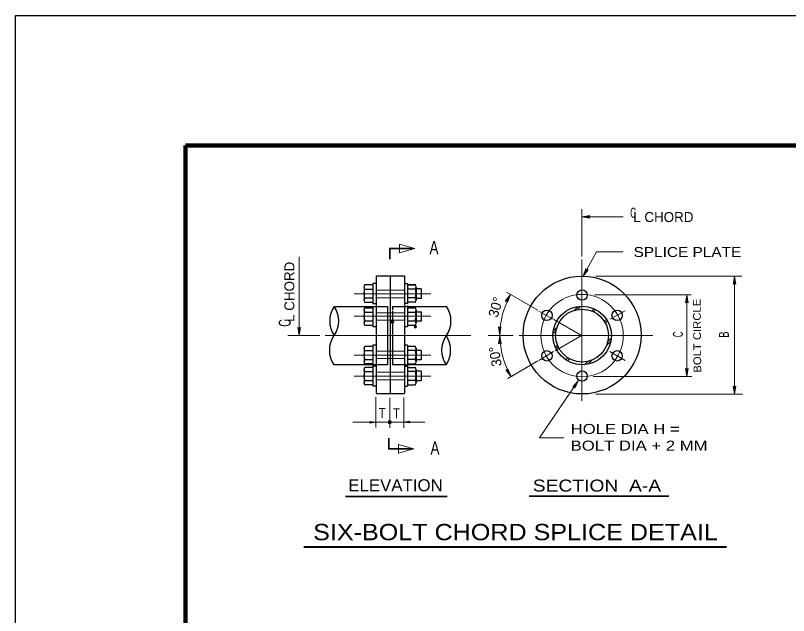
# Model space of a CAD drawing. Extents: x 312601.858 to 312602.699, y 144420.109 to 144420.704.
# Drawn here: x 312601.8578 to 312602.0898, y 144420.5234 to 144420.7035 of the extents above; entities that cross this region are included whole.
import ezdxf
from ezdxf.enums import TextEntityAlignment as Align

# ---------------------------------------------------------------- set-up
doc = ezdxf.new("R2010")
doc.units = 0
doc.header["$LTSCALE"] = 0.0012
doc.header["$PDMODE"] = 32
doc.header["$PDSIZE"] = 0.0006
for name, pattern in [('DOT_DASHED', [7.7, 5, -1.2, 0.3, -1.2]), ('LONG_DASHED', [7.5, 6, -1.5]), ('MEDIUM_DASHED', [4.5, 3, -1.5]), ('SHORT_DASHED', [2.7, 1.5, -1.2])]:
    doc.linetypes.add(name, pattern=pattern)
for name, color, linetype, lineweight in [('1', 7, 'Continuous', 25), ('2', 7, 'Continuous', 13), ('39', 7, 'Continuous', 13), ('9', 7, 'Continuous', 13)]:
    doc.layers.add(name, color=color, linetype=linetype, lineweight=lineweight)

msp = doc.modelspace()

# ---------------------------------------------------------------- hatches: boundary and pattern name
at = {"layer": '1'}
msp.add_hatch(color=256, dxfattribs=at).paths.add_polyline_path([(312601.97063, 144420.58144, 1), (312601.96961, 144420.58144, 1)])
at = {"layer": '39'}
for points in [[(312602.03, 144420.6431), (312602.0302, 144420.6427), (312602.0278, 144420.6431), (312602.0302, 144420.6435)], [(312602.0292, 144420.6272), (312602.0297, 144420.6272), (312602.0282, 144420.6253), (312602.029, 144420.6276)], [(312602.0736, 144420.6231), (312602.0732, 144420.6229), (312602.0736, 144420.6253), (312602.074, 144420.6229)], [(312602.0736, 144420.6231), (312602.0732, 144420.6229), (312602.0736, 144420.6253), (312602.074, 144420.6229)], [(312602.0053, 144420.6178), (312602.0048, 144420.6178), (312602.0064, 144420.6198), (312602.0055, 144420.6174)], [(312602.0593, 144420.6175), (312602.0589, 144420.6173), (312602.0593, 144420.6197), (312602.0597, 144420.6173)], [(312601.9429, 144420.6096), (312601.9433, 144420.6098), (312601.9429, 144420.6074), (312601.9425, 144420.6098)], [(312601.9429, 144420.6096), (312601.9433, 144420.6098), (312601.9429, 144420.6074), (312601.9425, 144420.6098)], [(312602.0032, 144420.6097), (312602.0035, 144420.61), (312602.0032, 144420.6074), (312602.0028, 144420.61)], [(312602.0032, 144420.6051), (312602.0028, 144420.6049), (312602.0032, 144420.6074), (312602.0036, 144420.6049)], [(312602.0054, 144420.5971), (312602.0056, 144420.5974), (312602.0066, 144420.595), (312602.005, 144420.5971)], [(312602.0593, 144420.5973), (312602.0597, 144420.5975), (312602.0593, 144420.5951), (312602.0589, 144420.5975)], [(312602.0255, 144420.592), (312602.0251, 144420.592), (312602.0267, 144420.5938), (312602.0257, 144420.5916)], [(312602.0255, 144420.592), (312602.0251, 144420.592), (312602.0267, 144420.5938), (312602.0257, 144420.5916)], [(312602.0736, 144420.592), (312602.074, 144420.5922), (312602.0736, 144420.5898), (312602.0732, 144420.5922)], [(312602.0736, 144420.592), (312602.074, 144420.5922), (312602.0736, 144420.5898), (312602.0732, 144420.5922)]]:
    msp.add_hatch(color=256, dxfattribs=at).paths.add_polyline_path(points)

# ---------------------------------------------------------------- linework, layer by layer
at = {"layer": '1', "lineweight": 13}
for p, q in [((312602.0278, 144420.6312), (312602.0278, 144420.6454)), ((312602.0278, 144420.6431), (312602.0402, 144420.6431)), ((312601.9429, 144420.6074), (312601.9429, 144420.6311)), ((312602.0322, 144420.6326), (312602.0282, 144420.6253)), ((312602.0322, 144420.6326), (312602.0402, 144420.6326)), ((312602.032, 144420.6253), (312602.0758, 144420.6253)), ((312602.0736, 144420.5898), (312602.0736, 144420.6253)), ((312601.9795, 144420.6213), (312601.9795, 144420.6215)), ((312602.0146, 144420.6151), (312602.0052, 144420.6205)), ((312602.0316, 144420.6197), (312602.0606, 144420.6197)), ((312602.0593, 144420.5951), (312602.0593, 144420.6197)), ((312601.9744, 144420.6162), (312601.9745, 144420.6162)), ((312602.0277, 144420.6074), (312602.0194, 144420.6122)), ((312601.9997, 144420.6074), (312602.0072, 144420.6074)), ((312602.0277, 144420.6074), (312602.0198, 144420.6028)), ((312601.9795, 144420.6028), (312601.9795, 144420.6029)), ((312601.9771, 144420.5989), (312601.9754, 144420.5989)), ((312602.0146, 144420.5998), (312602.0056, 144420.5945)), ((312601.9795, 144420.5965), (312601.9795, 144420.5967)), ((312602.0312, 144420.5951), (312602.0608, 144420.5951)), ((312602.0151, 144420.5767), (312602.0267, 144420.5938)), ((312602.032, 144420.5898), (312602.076, 144420.5898)), ((312601.9659, 144420.5889), (312601.9659, 144420.5798)), ((312601.9701, 144420.5887), (312601.9701, 144420.5797)), ((312601.9743, 144420.5888), (312601.9743, 144420.5797)), ((312601.959, 144420.5814), (312601.9806, 144420.5814))]:
    msp.add_line(p, q, dxfattribs=at)
at = {"layer": '1', "linetype": 'DOT_DASHED', "lineweight": 13}
for p, q in [((312602.0278, 144420.5878), (312602.0278, 144420.6303)), ((312602.0278, 144420.6171), (312602.0278, 144420.6224)), ((312601.9825, 144420.62), (312601.9594, 144420.62)), ((312602.0192, 144420.6123), (312602.0149, 144420.6148)), ((312602.0362, 144420.6123), (312602.0408, 144420.6149)), ((312601.9594, 144420.6132), (312601.9825, 144420.6132)), ((312602.009, 144420.6074), (312602.0491, 144420.6074)), ((312601.9594, 144420.6015), (312601.9825, 144420.6015)), ((312602.0193, 144420.6026), (312602.0149, 144420.5999)), ((312602.0362, 144420.6026), (312602.0408, 144420.5999)), ((312602.0278, 144420.5977), (312602.0278, 144420.5925)), ((312601.9825, 144420.5952), (312601.9594, 144420.5952))]:
    msp.add_line(p, q, dxfattribs=at)
at = {"layer": '1'}
for p, q in [((312601.966, 144420.6254), (312601.9745, 144420.6254)), ((312601.9745, 144420.6254), (312601.9745, 144420.6162)), ((312601.9624, 144420.622), (312601.9624, 144420.6181)), ((312601.965, 144420.6227), (312601.9626, 144420.6227)), ((312601.965, 144420.6231), (312601.965, 144420.6215)), ((312601.966, 144420.6231), (312601.965, 144420.6231)), ((312601.9745, 144420.6231), (312601.9754, 144420.6231)), ((312601.9754, 144420.6231), (312601.9754, 144420.6215)), ((312601.9754, 144420.6227), (312601.9778, 144420.6227)), ((312601.9779, 144420.6227), (312601.9754, 144420.6227)), ((312601.978, 144420.622), (312601.978, 144420.6181)), ((312601.9626, 144420.6214), (312601.965, 144420.6214)), ((312601.965, 144420.6215), (312601.965, 144420.6171)), ((312601.966, 144420.621), (312601.966, 144420.6162)), ((312601.9754, 144420.6215), (312601.9754, 144420.6171)), ((312601.9779, 144420.6214), (312601.9754, 144420.6214)), ((312601.9795, 144420.6215), (312601.978, 144420.6215)), ((312601.9795, 144420.6215), (312601.9795, 144420.6186)), ((312601.9625, 144420.6175), (312601.965, 144420.6175)), ((312601.9626, 144420.6188), (312601.965, 144420.6188)), ((312601.965, 144420.6171), (312601.966, 144420.6171)), ((312601.9754, 144420.6171), (312601.9745, 144420.6171)), ((312601.9778, 144420.6188), (312601.9754, 144420.6188)), ((312601.9779, 144420.6175), (312601.9754, 144420.6175)), ((312601.9795, 144420.6186), (312601.978, 144420.6186)), ((312601.9535, 144420.6162), (312601.966, 144420.6162)), ((312601.9624, 144420.6151), (312601.9624, 144420.6112)), ((312601.9626, 144420.6162), (312601.965, 144420.6162)), ((312601.9626, 144420.6158), (312601.965, 144420.6158)), ((312601.965, 144420.6162), (312601.965, 144420.6101)), ((312601.9745, 144420.6162), (312601.9873, 144420.6162)), ((312601.9754, 144420.6165), (312601.9754, 144420.6164)), ((312601.9754, 144420.6162), (312601.9754, 144420.6101)), ((312601.9754, 144420.6158), (312601.9778, 144420.6158)), ((312601.978, 144420.6151), (312601.978, 144420.6112)), ((312601.9626, 144420.6145), (312601.965, 144420.6145)), ((312601.9754, 144420.6145), (312601.9778, 144420.6145)), ((312601.9626, 144420.6118), (312601.965, 144420.6118)), ((312601.9626, 144420.6105), (312601.965, 144420.6105)), ((312601.965, 144420.6104), (312601.965, 144420.6101)), ((312601.965, 144420.6101), (312601.966, 144420.6101)), ((312601.966, 144420.6118), (312601.966, 144420.6115)), ((312601.966, 144420.6115), (312601.966, 144420.5901)), ((312601.9702, 144420.6118), (312601.9702, 144420.6115)), ((312601.9702, 144420.6115), (312601.9702, 144420.59)), ((312601.9745, 144420.6117), (312601.9745, 144420.6114)), ((312601.9745, 144420.6114), (312601.9745, 144420.5901)), ((312601.9745, 144420.6101), (312601.9754, 144420.6101)), ((312601.9754, 144420.6118), (312601.9778, 144420.6118)), ((312601.9754, 144420.6106), (312601.9754, 144420.6103)), ((312601.9754, 144420.6105), (312601.9778, 144420.6105)), ((312601.9624, 144420.6035), (312601.9624, 144420.5995)), ((312601.965, 144420.6041), (312601.9626, 144420.6041)), ((312601.966, 144420.6045), (312601.965, 144420.6045)), ((312601.9754, 144420.6045), (312601.9745, 144420.6045)), ((312601.9778, 144420.6041), (312601.9754, 144420.6041)), ((312601.978, 144420.6035), (312601.978, 144420.5995)), ((312601.9626, 144420.6029), (312601.965, 144420.6029)), ((312601.9779, 144420.6029), (312601.9754, 144420.6029)), ((312601.9795, 144420.6029), (312601.978, 144420.6029)), ((312601.978, 144420.6001), (312601.978, 144420.6029)), ((312601.9795, 144420.6029), (312601.9795, 144420.6001)), ((312601.965, 144420.5986), (312601.9534, 144420.5986)), ((312601.9626, 144420.6002), (312601.965, 144420.6002)), ((312601.965, 144420.5989), (312601.9626, 144420.5989)), ((312601.966, 144420.5985), (312601.965, 144420.5985)), ((312601.9754, 144420.5985), (312601.9745, 144420.5985)), ((312601.9778, 144420.6002), (312601.9754, 144420.6002)), ((312601.9754, 144420.5989), (312601.9778, 144420.5989)), ((312601.987, 144420.5986), (312601.9754, 144420.5986)), ((312601.9795, 144420.6001), (312601.978, 144420.6001)), ((312601.9624, 144420.5972), (312601.9624, 144420.5933)), ((312601.965, 144420.5978), (312601.9626, 144420.5978)), ((312601.9626, 144420.5966), (312601.965, 144420.5966)), ((312601.966, 144420.5982), (312601.965, 144420.5982)), ((312601.9745, 144420.5982), (312601.9754, 144420.5982)), ((312601.9754, 144420.5978), (312601.9778, 144420.5978)), ((312601.9779, 144420.5966), (312601.9754, 144420.5966)), ((312601.978, 144420.5972), (312601.978, 144420.5933)), ((312601.9795, 144420.5967), (312601.978, 144420.5967)), ((312601.9795, 144420.5967), (312601.9795, 144420.5938)), ((312601.9626, 144420.5939), (312601.965, 144420.5939)), ((312601.9778, 144420.5939), (312601.9754, 144420.5939)), ((312601.965, 144420.5926), (312601.9626, 144420.5926)), ((312601.966, 144420.5922), (312601.965, 144420.5922)), ((312601.9745, 144420.5922), (312601.9754, 144420.5922)), ((312601.9754, 144420.5926), (312601.9778, 144420.5926)), ((312601.9795, 144420.5938), (312601.978, 144420.5938)), ((312601.966, 144420.59), (312601.9745, 144420.59))]:
    msp.add_line(p, q, dxfattribs=at)
at = {"layer": '1', "linetype": 'MEDIUM_DASHED', "lineweight": 13}
for p, q in [((312601.9745, 144420.6211), (312601.966, 144420.6211)), ((312601.9745, 144420.6188), (312601.966, 144420.6188)), ((312601.9662, 144420.6143), (312601.9743, 144420.6143)), ((312601.9663, 144420.612), (312601.9743, 144420.612)), ((312601.9746, 144420.6027), (312601.9661, 144420.6027)), ((312601.9747, 144420.6005), (312601.9662, 144420.6005)), ((312601.9744, 144420.5964), (312601.9659, 144420.5964)), ((312601.9745, 144420.5941), (312601.966, 144420.5941))]:
    msp.add_line(p, q, dxfattribs=at)
at = {"layer": '1', "linetype": 'LONG_DASHED'}
for p, q in [((312601.9653, 144420.6162), (312601.9694, 144420.6162)), ((312601.9709, 144420.6162), (312601.9752, 144420.6162)), ((312601.9709, 144420.6162), (312601.9709, 144420.6151)), ((312601.9709, 144420.6148), (312601.9709, 144420.6114)), ((312601.9694, 144420.6118), (312601.9694, 144420.6115)), ((312601.9694, 144420.6115), (312601.9694, 144420.5986)), ((312601.9709, 144420.6117), (312601.9709, 144420.6114)), ((312601.9709, 144420.6114), (312601.9709, 144420.5986)), ((312601.9694, 144420.5986), (312601.9654, 144420.5986)), ((312601.975, 144420.5986), (312601.9709, 144420.5986))]:
    msp.add_line(p, q, dxfattribs=at)
at = {"layer": '1', "linetype": 'SHORT_DASHED', "lineweight": 13}
msp.add_line((312601.9754, 144420.5989), (312601.9771, 144420.5989), dxfattribs=at)
at = {"layer": '1', "lineweight": 35}
for points in [[(312601.9771, 144420.6336), (312601.9701, 144420.6336), (312601.9701, 144420.6304)], [(312601.9768, 144420.5734), (312601.9698, 144420.5734), (312601.9698, 144420.5766)]]:
    msp.add_lwpolyline(points, dxfattribs=at)
at = {"layer": '1'}
for points in [[(312601.966, 144420.6254), (312601.966, 144420.6237), (312601.966, 144420.621)], [(312601.9702, 144420.6254), (312601.9702, 144420.6151), (312601.9702, 144420.6115)], [(312601.966, 144420.6162), (312601.966, 144420.6151), (312601.966, 144420.6115)], [(312601.9745, 144420.6162), (312601.9745, 144420.6151), (312601.9745, 144420.6114)], [(312601.965, 144420.6045), (312601.965, 144420.5985), (312601.965, 144420.5922)], [(312601.9754, 144420.6045), (312601.9754, 144420.5985), (312601.9754, 144420.5922)]]:
    msp.add_lwpolyline(points, dxfattribs=at)
at = {"layer": '1', "linetype": 'LONG_DASHED'}
msp.add_lwpolyline([(312601.9694, 144420.6162), (312601.9694, 144420.6151), (312601.9694, 144420.6115)], dxfattribs=at)
at = {"layer": '1'}
for centre, radius in [((312602.02783, 144420.60759), 0.017693), ((312602.02783, 144420.619575), 0.00156), ((312602.017303, 144420.613498), 0.00156), ((312602.02783, 144420.60742), 0.008788), ((312602.02783, 144420.60742), 0.007942), ((312602.038357, 144420.613498), 0.00156), ((312602.017303, 144420.601343), 0.00156), ((312602.038357, 144420.601343), 0.00156), ((312602.02783, 144420.595265), 0.00156)]:
    msp.add_circle(centre, radius, dxfattribs=at)
at = {"layer": '1', "linetype": 'DOT_DASHED', "lineweight": 13}
msp.add_circle((312602.02783, 144420.60742), 0.012354, dxfattribs=at)
at = {"layer": '1', "lineweight": 13}
msp.add_circle((312601.97012, 144420.58144), 0.00051, dxfattribs=at)
at = {"layer": '1'}
for centre, radius, start, end in [((312601.96349, 144420.621985), 0.001105, 142.02013, 212.47565), ((312601.97692, 144420.621985), 0.001105, 327.52435, 37.97987), ((312601.97386, 144420.6202), 0.004169, 339.71744, 16.58734), ((312601.96349, 144420.618075), 0.001105, 142.02013, 211.35654), ((312601.97692, 144420.618075), 0.001105, 328.64346, 37.97987), ((312601.96349, 144420.615155), 0.001105, 144.28806, 217.97987), ((312601.97692, 144420.615165), 0.001105, 323.00036, 35.07587), ((312601.96655, 144420.61328), 0.004169, 162.98192, 200.79629), ((312601.97386, 144420.61328), 0.004169, 339.98134, 17.62585), ((312601.96349, 144420.611155), 0.001105, 142.02013, 217.97987), ((312601.97692, 144420.611155), 0.001105, 322.02013, 35.71194), ((312601.96349, 144420.603455), 0.001105, 142.02013, 212.47565), ((312601.97692, 144420.603455), 0.001105, 327.52435, 37.97987), ((312601.96655, 144420.60167), 0.004169, 163.41266, 200.28256), ((312601.97386, 144420.60167), 0.004169, 339.71744, 16.58734), ((312601.96349, 144420.599545), 0.001105, 142.02013, 217.97987), ((312601.97692, 144420.599545), 0.001105, 322.02013, 37.97987), ((312601.96655, 144420.59538), 0.004169, 163.41266, 200.28256), ((312601.96349, 144420.597165), 0.001105, 144.92413, 212.47565), ((312601.97386, 144420.59538), 0.004169, 339.71744, 16.58734), ((312601.97692, 144420.597165), 0.001105, 327.52435, 35.07587), ((312601.96349, 144420.593255), 0.001105, 142.02013, 217.97987), ((312601.97692, 144420.593255), 0.001105, 322.02013, 37.97987)]:
    msp.add_arc(centre, radius, start, end, dxfattribs=at)
at = {"layer": '1', "lineweight": 13}
for centre, radius, start, end in [((312601.96655, 144420.6202), 0.004169, 163.41266, 200.28256), ((312602.02783, 144420.60759), 0.024638, 150.28424, 180.39609), ((312602.02783, 144420.60759), 0.024638, 180.39533, 210.59712)]:
    msp.add_arc(centre, radius, start, end, dxfattribs=at)
at = {"layer": '1'}
for p in [(312601.9709, 144420.6115), (312601.9709, 144420.6114)]:
    msp.add_point(p, dxfattribs=at)
at = {"layer": '2'}
for p, q in [((312602.0255, 144420.615), (312602.0266, 144420.6161)), ((312602.0264, 144420.6152), (312602.0274, 144420.6162)), ((312602.0308, 144420.6148), (312602.0314, 144420.6154)), ((312602.0313, 144420.6146), (312602.0319, 144420.6152)), ((312602.0346, 144420.6117), (312602.0352, 144420.6123)), ((312602.0349, 144420.6112), (312602.0355, 144420.6118)), ((312602.0191, 144420.6086), (312602.0203, 144420.6098)), ((312602.0191, 144420.6079), (312602.0201, 144420.6089)), ((312601.9395, 144420.6074), (312601.9491, 144420.6074)), ((312602.0352, 144420.6044), (312602.0364, 144420.6056)), ((312602.0355, 144420.6055), (312602.0366, 144420.6066)), ((312602.0198, 144420.6038), (312602.0205, 144420.6045)), ((312602.02, 144420.6033), (312602.0207, 144420.604)), ((312602.023, 144420.6001), (312602.0236, 144420.6007)), ((312602.0235, 144420.5998), (312602.0241, 144420.6004)), ((312602.0286, 144420.5986), (312602.0297, 144420.5997)), ((312602.0296, 144420.5988), (312602.0309, 144420.6001)), ((312602.0224, 144420.5767), (312602.0151, 144420.5767))]:
    msp.add_line(p, q, dxfattribs=at)
at = {"layer": '2', "linetype": 'DOT_DASHED'}
msp.add_line((312601.9507, 144420.6074), (312601.9945, 144420.6074), dxfattribs=at)
at = {"layer": '2', "lineweight": 35}
for p, q in [((312601.9568, 144420.5591), (312601.9874, 144420.5591)), ((312602.012, 144420.5592), (312602.0539, 144420.5592))]:
    msp.add_line(p, q, dxfattribs=at)
at = {"layer": '2', "lineweight": 40}
msp.add_line((312601.9443, 144420.544), (312602.0712, 144420.544), dxfattribs=at)
at = {"layer": '2'}
for points in [[(312602.0284, 144420.6256), (312602.0283, 144420.6254), (312602.0283, 144420.6256), (312602.0283, 144420.6256)], [(312601.9641, 144420.5816), (312601.966, 144420.5814), (312601.9641, 144420.5811), (312601.9643, 144420.5814)], [(312601.9761, 144420.5812), (312601.9742, 144420.5814), (312601.9761, 144420.5817), (312601.9759, 144420.5814)], [(312601.9761, 144420.5812), (312601.9742, 144420.5814), (312601.9761, 144420.5817), (312601.9759, 144420.5814)]]:
    msp.add_lwpolyline(points, close=True, dxfattribs=at)
at = {"layer": '2', "lineweight": 25}
msp.add_lwpolyline([(312601.978, 144420.6146), (312601.9795, 144420.6146), (312601.9795, 144420.6117), (312601.978, 144420.6117)], dxfattribs=at)
for centre, radius, start, end in [((312601.960192, 144420.6118), 0.008093, 147.06517, 212.93482), ((312601.947186, 144420.6118), 0.007614, 324.69975, 35.30025), ((312601.980408, 144420.6118), 0.008093, 327.06517, 32.93482), ((312601.960092, 144420.603), 0.008093, 147.06517, 212.93482), ((312601.993314, 144420.603), 0.007614, 144.69975, 215.30025), ((312601.980308, 144420.603), 0.008093, 327.06517, 32.93482)]:
    msp.add_arc(centre, radius, start, end, dxfattribs=at)
at = {"layer": '2'}
for p in [(312601.9778, 144420.6101), (312601.9778, 144420.61)]:
    msp.add_point(p, dxfattribs=at)
at = {"layer": '39', "lineweight": 25}
for p, q in [((312601.8578, 144420.1095), (312601.8578, 144420.7035)), ((312601.8578, 144420.7035), (312602.6988, 144420.7035))]:
    msp.add_line(p, q, dxfattribs=at)
at = {"layer": '39', "lineweight": 158}
for p, q in [((312601.9088, 144420.1247), (312601.9088, 144420.6645)), ((312601.9088, 144420.6645), (312602.6838, 144420.6645))]:
    msp.add_line(p, q, dxfattribs=at)
at = {"layer": '39'}
for points in [[(312602.03, 144420.6431), (312602.0302, 144420.6427), (312602.0278, 144420.6431), (312602.0302, 144420.6435)], [(312602.0292, 144420.6272), (312602.0297, 144420.6272), (312602.0282, 144420.6253), (312602.029, 144420.6276)], [(312602.0736, 144420.6231), (312602.0732, 144420.6229), (312602.0736, 144420.6253), (312602.074, 144420.6229)], [(312602.0736, 144420.6231), (312602.0732, 144420.6229), (312602.0736, 144420.6253), (312602.074, 144420.6229)], [(312602.0053, 144420.6178), (312602.0048, 144420.6178), (312602.0064, 144420.6198), (312602.0055, 144420.6174)], [(312602.0593, 144420.6175), (312602.0589, 144420.6173), (312602.0593, 144420.6197), (312602.0597, 144420.6173)], [(312601.9429, 144420.6096), (312601.9433, 144420.6098), (312601.9429, 144420.6074), (312601.9425, 144420.6098)], [(312601.9429, 144420.6096), (312601.9433, 144420.6098), (312601.9429, 144420.6074), (312601.9425, 144420.6098)], [(312602.0032, 144420.6097), (312602.0035, 144420.61), (312602.0032, 144420.6074), (312602.0028, 144420.61)], [(312602.0032, 144420.6051), (312602.0028, 144420.6049), (312602.0032, 144420.6074), (312602.0036, 144420.6049)], [(312602.0054, 144420.5971), (312602.0056, 144420.5974), (312602.0066, 144420.595), (312602.005, 144420.5971)], [(312602.0593, 144420.5973), (312602.0597, 144420.5975), (312602.0593, 144420.5951), (312602.0589, 144420.5975)], [(312602.0255, 144420.592), (312602.0251, 144420.592), (312602.0267, 144420.5938), (312602.0257, 144420.5916)], [(312602.0255, 144420.592), (312602.0251, 144420.592), (312602.0267, 144420.5938), (312602.0257, 144420.5916)], [(312602.0736, 144420.592), (312602.074, 144420.5922), (312602.0736, 144420.5898), (312602.0732, 144420.5922)], [(312602.0736, 144420.592), (312602.074, 144420.5922), (312602.0736, 144420.5898), (312602.0732, 144420.5922)]]:
    msp.add_lwpolyline(points, close=True, dxfattribs=at)
at = {"layer": '9'}
for points in [[(312601.973, 144420.6323), (312601.9776, 144420.6336), (312601.973, 144420.6349)], [(312601.9727, 144420.5721), (312601.9773, 144420.5734), (312601.9727, 144420.5747)]]:
    msp.add_lwpolyline(points, close=True, dxfattribs=at)

# ---------------------------------------------------------------- texts
at = {"layer": '2'}
for s, width, p in [('C', 0.6, (312602.0423, 144420.6428)), ('HOLE DIA H = ', 1.25, (312602.0244, 144420.5779)), ('BOLT DIA + 2 MM', 1.25, (312602.0244, 144420.5729))]:
    msp.add_text(s, height=0.003, dxfattribs=dict(at, width=width)).set_placement(p)
msp.add_text('L CHORD', height=0.003, dxfattribs=at).set_placement((312602.0432, 144420.6415))
for s, height, width, p in [('A', 0.004, 0.75, (312601.9834, 144420.6318)), ('SPLICE PLATE', 0.003, 1.15, (312602.05945, 144420.631)), ('T', 0.003, 0.8, (312601.96785, 144420.5827)), ('T', 0.003, 0.8, (312601.97215, 144420.5826)), ('A', 0.004, 0.75, (312601.9837, 144420.5717)), ('ELEVATION', 0.0036, 1.05, (312601.97185, 144420.5607)), ('SECTION  A-A', 0.0036, 1.2, (312602.0323, 144420.5606)), ('SIX-BOLT CHORD SPLICE DETAIL', 0.0049, 1.15, (312602.00785, 144420.546))]:
    msp.add_text(s, height=height, dxfattribs=dict(at, width=width)).set_placement(p, align=Align.CENTER)
for s, rotation, p in [('L CHORD', 90, (312601.9415, 144420.62055)), ('30°', 73.409, (312602.003349, 144420.615522)), ('30°', 98.865, (312602.003275, 144420.601369))]:
    msp.add_text(s, height=0.003, rotation=rotation, dxfattribs=at).set_placement(p, align=Align.CENTER)
at = {"layer": '2', "width": 1.1}
msp.add_text('BOLT CIRCLE', height=0.0023, rotation=90.492, dxfattribs=at).set_placement((312602.0636, 144420.5963))
at = {"layer": '2'}
for s, height, width, p in [('C', 0.0036, 0.65, (312601.9404, 144420.6112)), ('C', 0.003, 0.6, (312602.0581, 144420.6078)), ('B', 0.003, 0.7, (312602.0719, 144420.6077))]:
    msp.add_text(s, height=height, rotation=90, dxfattribs=dict(at, width=width)).set_placement(p, align=Align.CENTER)

doc.saveas('drawing.dxf')
